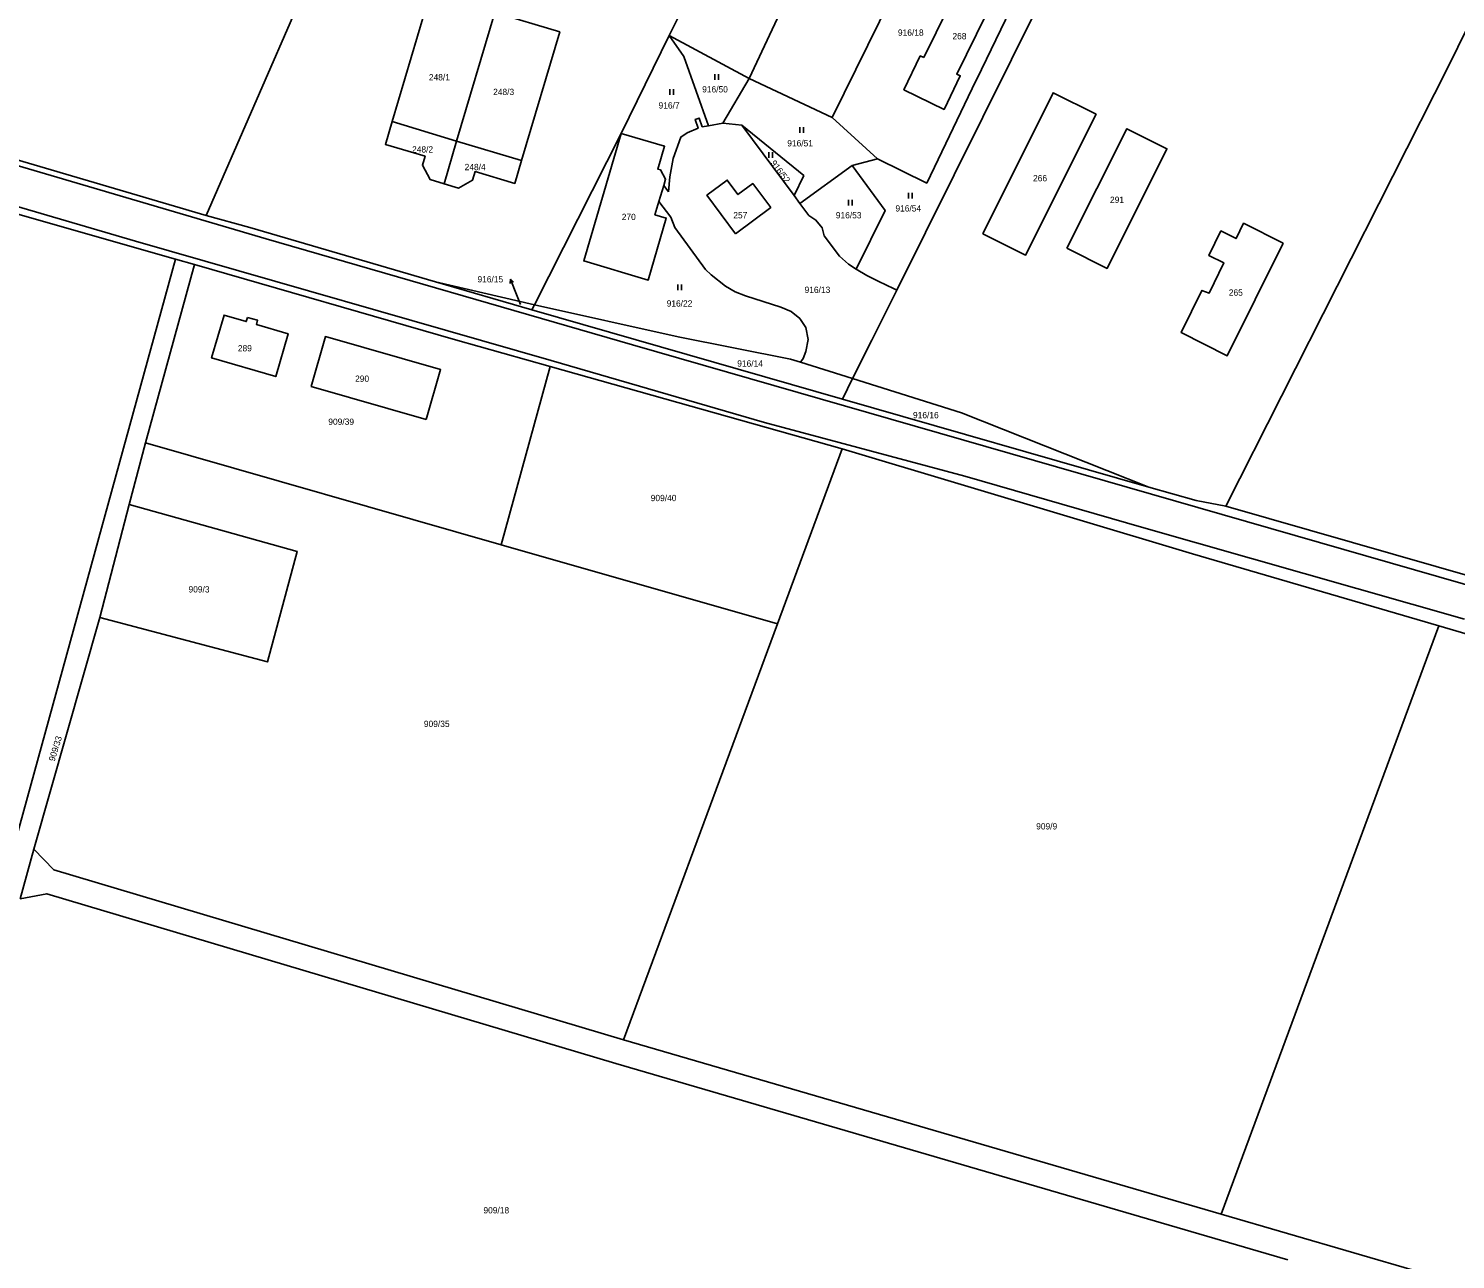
# Model space of a CAD drawing. Extents: x -7476540 to -746055, y -11317203 to -1129777.
# Drawn here: x -750408.5 to -750022.6, y -1131564.4 to -1131231.7 of the extents above; entities that cross this region are included whole.
import ezdxf

# ---------------------------------------------------------------- set-up
doc = ezdxf.new("R2010")
doc.units = 0
for name, color, linetype in [('Hranice parcel', 7, 'Continuous'), ('Parcelní čísla', 7, 'Continuous'), ('Pop  PČ popisy', 7, 'Continuous'), ('Vnitřní kresba', 7, 'Continuous'), ('Značky kultur', 7, 'Continuous')]:
    doc.layers.add(name, color=color, linetype=linetype)

msp = doc.modelspace()

# ---------------------------------------------------------------- linework, layer by layer
at = {"layer": 'Hranice parcel'}
for p, q in [((-750213.6, -1131245.21), (-750183.36, -1131180.54)), ((-750235.23, -1131233.64), (-750213.06, -1131188.66)), ((-750324.56, -1131199.94), (-750360.45, -1131282.22)), ((-750191.14, -1131255.75), (-750164.85, -1131202.13)), ((-750292.72, -1131262.14), (-750282.4, -1131227.41)), ((-750528.14, -1131233.04), (-750360.45, -1131282.22)), ((-750248.26, -1131260.08), (-750235.23, -1131233.64)), ((-750213.6, -1131245.21), (-750235.23, -1131233.64)), ((-750231.31, -1131239.24), (-750235.23, -1131233.64)), ((-750224.57, -1131257.99), (-750231.31, -1131239.24)), ((-750220.69, -1131257.3), (-750213.6, -1131245.21)), ((-750191.14, -1131255.75), (-750213.6, -1131245.21)), ((-750310.14, -1131256.86), (-750292.72, -1131262.14)), ((-750220.69, -1131257.3), (-750224.57, -1131257.99)), ((-750215.6, -1131257.81), (-750220.69, -1131257.3)), ((-750201.48, -1131276.85), (-750215.6, -1131257.81)), ((-750191.14, -1131255.75), (-750178.9, -1131266.92)), ((-750296.07, -1131273.69), (-750292.72, -1131262.14)), ((-750292.72, -1131262.14), (-750275.17, -1131267.37)), ((-750271.68, -1131306.39), (-750248.26, -1131260.08)), ((-750199.88, -1131279.01), (-750185.76, -1131268.74)), ((-750185.76, -1131268.74), (-750178.9, -1131266.92)), ((-750238.02, -1131278.51), (-750236.72, -1131274.17)), ((-750236.72, -1131274.17), (-750235.44, -1131275.83)), ((-750368.77, -1131294.03), (-750429.73, -1131276.7)), ((-750199.88, -1131279.01), (-750201.48, -1131276.85)), ((-750238.02, -1131278.51), (-750234.83, -1131282.68)), ((-750376.86, -1131343.72), (-750363.58, -1131295.52)), ((-750363.58, -1131295.52), (-750368.77, -1131294.03)), ((-750181.78, -1131298.5), (-750184.65, -1131296.75)), ((-750298.46, -1131300.2), (-750271.68, -1131306.39)), ((-750298.46, -1131300.2), (-750272.39, -1131307.79)), ((-750272.39, -1131307.79), (-750271.68, -1131306.39)), ((-750272.39, -1131307.79), (-750188.4, -1131331.9)), ((-750232.83, -1131315.05), (-750271.68, -1131306.39)), ((-750280.72, -1131371.25), (-750267.44, -1131323.05)), ((-750267.44, -1131323.05), (-750188.41, -1131345.3)), ((-750199.74, -1131321.89), (-750185.65, -1131326.3)), ((-750188.4, -1131331.9), (-750185.65, -1131326.3)), ((-750185.65, -1131326.3), (-750156.2, -1131335.62)), ((-750188.4, -1131331.9), (-750105.48, -1131355.7)), ((-750156.2, -1131335.62), (-750105.48, -1131355.7)), ((-750381.31, -1131360.4), (-750376.86, -1131343.72)), ((-750280.72, -1131371.25), (-750376.86, -1131343.72)), ((-750205.95, -1131392.66), (-750188.41, -1131345.3)), ((-750381.31, -1131360.4), (-750389.25, -1131390.88)), ((-750205.95, -1131392.66), (-750280.72, -1131371.25)), ((-750407.11, -1131453.55), (-750389.25, -1131390.88)), ((-750247.56, -1131505.04), (-750205.95, -1131392.66)), ((-750027.07, -1131393.19), (-750085.94, -1131552.16)), ((-750410.8, -1131466.96), (-750407.11, -1131453.55)), ((-750085.94, -1131552.16), (-750247.56, -1131505.04)), ((-749969.59, -1131586.07), (-750085.94, -1131552.16))]:
    msp.add_line(p, q, dxfattribs=at)
for points in [[(-750084.66, -1131360.85), (-750024.43, -1131241.89), (-749966.16, -1131123.14)], [(-750178.9, -1131266.92), (-750165.58, -1131273.52), (-750152.27, -1131245.87), (-750152.05, -1131245.42), (-750137.8, -1131215.82)], [(-750166.39, -1131239.57), (-750167.34, -1131239.11), (-750171.77, -1131248.26), (-750160.9, -1131253.58), (-750156.52, -1131244.49), (-750157.47, -1131244.03), (-750144.17, -1131217.03), (-750153.14, -1131212.62), (-750166.39, -1131239.57)], [(-750131.95, -1131218.45), (-750134.94, -1131224.54), (-750173.68, -1131302.46)], [(-750282.4, -1131227.41), (-750299.84, -1131222.2), (-750310.14, -1131256.86)], [(-750275.17, -1131267.37), (-750264.83, -1131232.64), (-750282.4, -1131227.41)], [(-750150.44, -1131287.18), (-750138.87, -1131292.97), (-750119.76, -1131254.89), (-750131.39, -1131249.08), (-750150.44, -1131287.18)], [(-750310.14, -1131256.86), (-750311.97, -1131263.05), (-750301.25, -1131266.23), (-750301.96, -1131268.62), (-750299.91, -1131272.53), (-750296.07, -1131273.69)], [(-750235.44, -1131275.83), (-750235.07, -1131271.78), (-750234.17, -1131266.81), (-750232.12, -1131261.08), (-750230.39, -1131259.96), (-750227.42, -1131258.67), (-750228.21, -1131256.31), (-750227.09, -1131255.91), (-750226.29, -1131258.29), (-750224.57, -1131257.99)], [(-750215.6, -1131257.81), (-750198.84, -1131271.46), (-750201.48, -1131276.85)], [(-750127.66, -1131291.13), (-750116.79, -1131296.55), (-750100.62, -1131264.23), (-750111.49, -1131258.8), (-750127.66, -1131291.13)], [(-750248.26, -1131260.08), (-750258.33, -1131294.52), (-750240.89, -1131299.71), (-750236.02, -1131282.98), (-750239.08, -1131282.06), (-750238.02, -1131278.51)], [(-750236.72, -1131274.17), (-750236.19, -1131272.42), (-750237.56, -1131269.94), (-750238.31, -1131269.72), (-750236.48, -1131263.55), (-750248.26, -1131260.08)], [(-750296.07, -1131273.69), (-750292.22, -1131274.84), (-750288.42, -1131272.75), (-750287.72, -1131270.38), (-750277.01, -1131273.57), (-750275.17, -1131267.37)], [(-750185.76, -1131268.74), (-750176.85, -1131280.89), (-750184.65, -1131296.75)], [(-750217.32, -1131287.2), (-750207.78, -1131280.08), (-750212.64, -1131273.63), (-750216.63, -1131276.61), (-750219.52, -1131272.67), (-750225.03, -1131276.8), (-750217.32, -1131287.2)], [(-750184.65, -1131296.75), (-750186.77, -1131295.46), (-750189.14, -1131293.25), (-750193.36, -1131287.8), (-750193.84, -1131285.62), (-750195.57, -1131283.49), (-750197.49, -1131282.23), (-750199.88, -1131279.01)], [(-750360.45, -1131282.22), (-750348.62, -1131285.5), (-750298.46, -1131300.2)], [(-750234.83, -1131282.68), (-750233.72, -1131285.51), (-750225.39, -1131296.89), (-750223.88, -1131298.31), (-750220.03, -1131301.39), (-750217.4, -1131302.86), (-750214.6, -1131303.99), (-750205.02, -1131307.02), (-750202.29, -1131308.25), (-750199.92, -1131310.11), (-750198.25, -1131312.57), (-750197.69, -1131315.75), (-750198.32, -1131319.01), (-750198.97, -1131320.91), (-750199.74, -1131321.89)], [(-750069.14, -1131289.7), (-750079.88, -1131284.36), (-750081.92, -1131288.48), (-750086.03, -1131286.44), (-750089.32, -1131293.05), (-750085.22, -1131295.1), (-750089.22, -1131303.28), (-750091.14, -1131302.52), (-750096.78, -1131313.88), (-750084.29, -1131320.16), (-750069.14, -1131289.7)], [(-750443.23, -1131564.35), (-750407.78, -1131435.86), (-750368.77, -1131294.03)], [(-750363.58, -1131295.52), (-750293.03, -1131315.85), (-750267.44, -1131323.05)], [(-750173.68, -1131302.46), (-750177.38, -1131300.65), (-750177.83, -1131300.43), (-750181.78, -1131298.5)], [(-750173.68, -1131302.46), (-750180.41, -1131315.97), (-750185.65, -1131326.3)], [(-750349.29, -1131309.79), (-750346.58, -1131310.57), (-750346.89, -1131311.71), (-750338.31, -1131314.21), (-750341.64, -1131325.78), (-750358.98, -1131320.76), (-750355.64, -1131309.19), (-750349.64, -1131310.93), (-750349.29, -1131309.79)], [(-750300.92, -1131337.38), (-750332.05, -1131328.47), (-750328.2, -1131315), (-750297.06, -1131323.92), (-750300.92, -1131337.38)], [(-750199.74, -1131321.89), (-750202.42, -1131321.06), (-750232.83, -1131315.05)], [(-750188.41, -1131345.3), (-750093.71, -1131373.73), (-750027.07, -1131393.19)], [(-750105.48, -1131355.7), (-750092.73, -1131359.32), (-750084.66, -1131360.85)], [(-750389.25, -1131390.88), (-750343.85, -1131402.94), (-750335.82, -1131373.07), (-750381.31, -1131360.4)], [(-749953.16, -1131398.66), (-749982.59, -1131390.14), (-750084.66, -1131360.85)], [(-750027.07, -1131393.19), (-749986.84, -1131404.94), (-749910.73, -1131427.13)], [(-750407.11, -1131453.55), (-750401.64, -1131459.15), (-750247.56, -1131505.04)], [(-750067.88, -1131564.53), (-750249.66, -1131511.44), (-750403.56, -1131465.6), (-750410.8, -1131466.96)]]:
    msp.add_lwpolyline(points, dxfattribs=at)
at = {"layer": 'Pop  PČ popisy'}
for p, q in [((-750278.19, -1131299.5), (-750278.28, -1131300.61)), ((-750277.07, -1131302.28), (-750278.19, -1131299.5)), ((-750278.19, -1131299.5), (-750277.35, -1131300.24)), ((-750275.43, -1131306.28), (-750277.07, -1131302.28))]:
    msp.add_line(p, q, dxfattribs=at)
at = {"layer": 'Vnitřní kresba'}
for p, q in [((-750344.21, -1131288.58), (-750506.88, -1131240.71)), ((-750379.57, -1131289.16), (-750480.64, -1131259.63)), ((-750267.13, -1131321.44), (-750379.57, -1131289.16)), ((-750245.14, -1131317.19), (-750344.21, -1131288.58)), ((-750085.67, -1131363.08), (-750245.14, -1131317.19)), ((-750209.48, -1131338.18), (-750267.13, -1131321.44)), ((-750155.3, -1131352.72), (-750209.48, -1131338.18)), ((-750106.84, -1131366.7), (-750155.3, -1131352.72)), ((-750020.17, -1131391.38), (-750106.84, -1131366.7)), ((-749959.52, -1131399.32), (-750085.67, -1131363.08))]:
    msp.add_line(p, q, dxfattribs=at)
at = {"layer": 'Značky kultur'}
for p, q in [((-750222.88, -1131245.56), (-750222.88, -1131244.06)), ((-750221.88, -1131245.56), (-750221.88, -1131244.06)), ((-750235.07, -1131249.65), (-750235.07, -1131248.15)), ((-750234.07, -1131249.65), (-750234.07, -1131248.15)), ((-750199.94, -1131259.9), (-750199.94, -1131258.4)), ((-750198.94, -1131259.9), (-750198.94, -1131258.4)), ((-750208.29, -1131266.63), (-750208.29, -1131265.13)), ((-750207.29, -1131266.63), (-750207.29, -1131265.13)), ((-750186.73, -1131279.52), (-750186.73, -1131278.02)), ((-750185.73, -1131279.52), (-750185.73, -1131278.02)), ((-750170.53, -1131277.65), (-750170.53, -1131276.15)), ((-750169.53, -1131277.65), (-750169.53, -1131276.15)), ((-750232.88, -1131302.43), (-750232.88, -1131300.93)), ((-750231.88, -1131302.43), (-750231.88, -1131300.93))]:
    msp.add_line(p, q, dxfattribs=at)

# ---------------------------------------------------------------- texts
at = {"layer": 'Parcelní čísla'}
for s, p in [('916/18', (-750173.37, -1131233.67)), ('268', (-750158.63, -1131234.64)), ('248/1', (-750300.23, -1131245.75)), ('916/50', (-750226.32, -1131249)), ('248/3', (-750282.86, -1131249.71)), ('916/7', (-750238.11, -1131253.35)), ('916/51', (-750203.3, -1131263.59)), ('248/2', (-750304.78, -1131265.24)), ('248/4', (-750290.56, -1131270.01)), ('266', (-750136.83, -1131273.03)), ('291', (-750116.02, -1131278.85)), ('270', (-750248.07, -1131283.5)), ('257', (-750217.9, -1131283.04)), ('916/53', (-750190.17, -1131283.04)), ('916/54', (-750174.05, -1131281.18)), ('916/15', (-750287.09, -1131300.35)), ('916/22', (-750235.92, -1131306.88)), ('916/13', (-750198.62, -1131303.19)), ('265', (-750083.88, -1131303.94)), ('289', (-750351.89, -1131318.99)), ('916/14', (-750216.83, -1131323.11)), ('290', (-750320.19, -1131327.22)), ('916/16', (-750169.3, -1131337.06)), ('909/39', (-750327.43, -1131338.85)), ('909/40', (-750240.23, -1131359.47)), ('909/3', (-750365.24, -1131384.16)), ('909/35', (-750301.58, -1131420.52)), ('909/9', (-750135.98, -1131448.21)), ('909/18', (-750285.48, -1131552))]:
    msp.add_text(s, height=1.7, dxfattribs=at).set_placement(p)
for s, rotation, p in [('916/52', 307, (-750207.91, -1131268.12)), ('909/33', 73, (-750401.47, -1131429.93))]:
    msp.add_text(s, height=1.7, rotation=rotation, dxfattribs=at).set_placement(p)

doc.saveas('drawing.dxf')
